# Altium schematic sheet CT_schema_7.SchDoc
size 372 x 245 mm
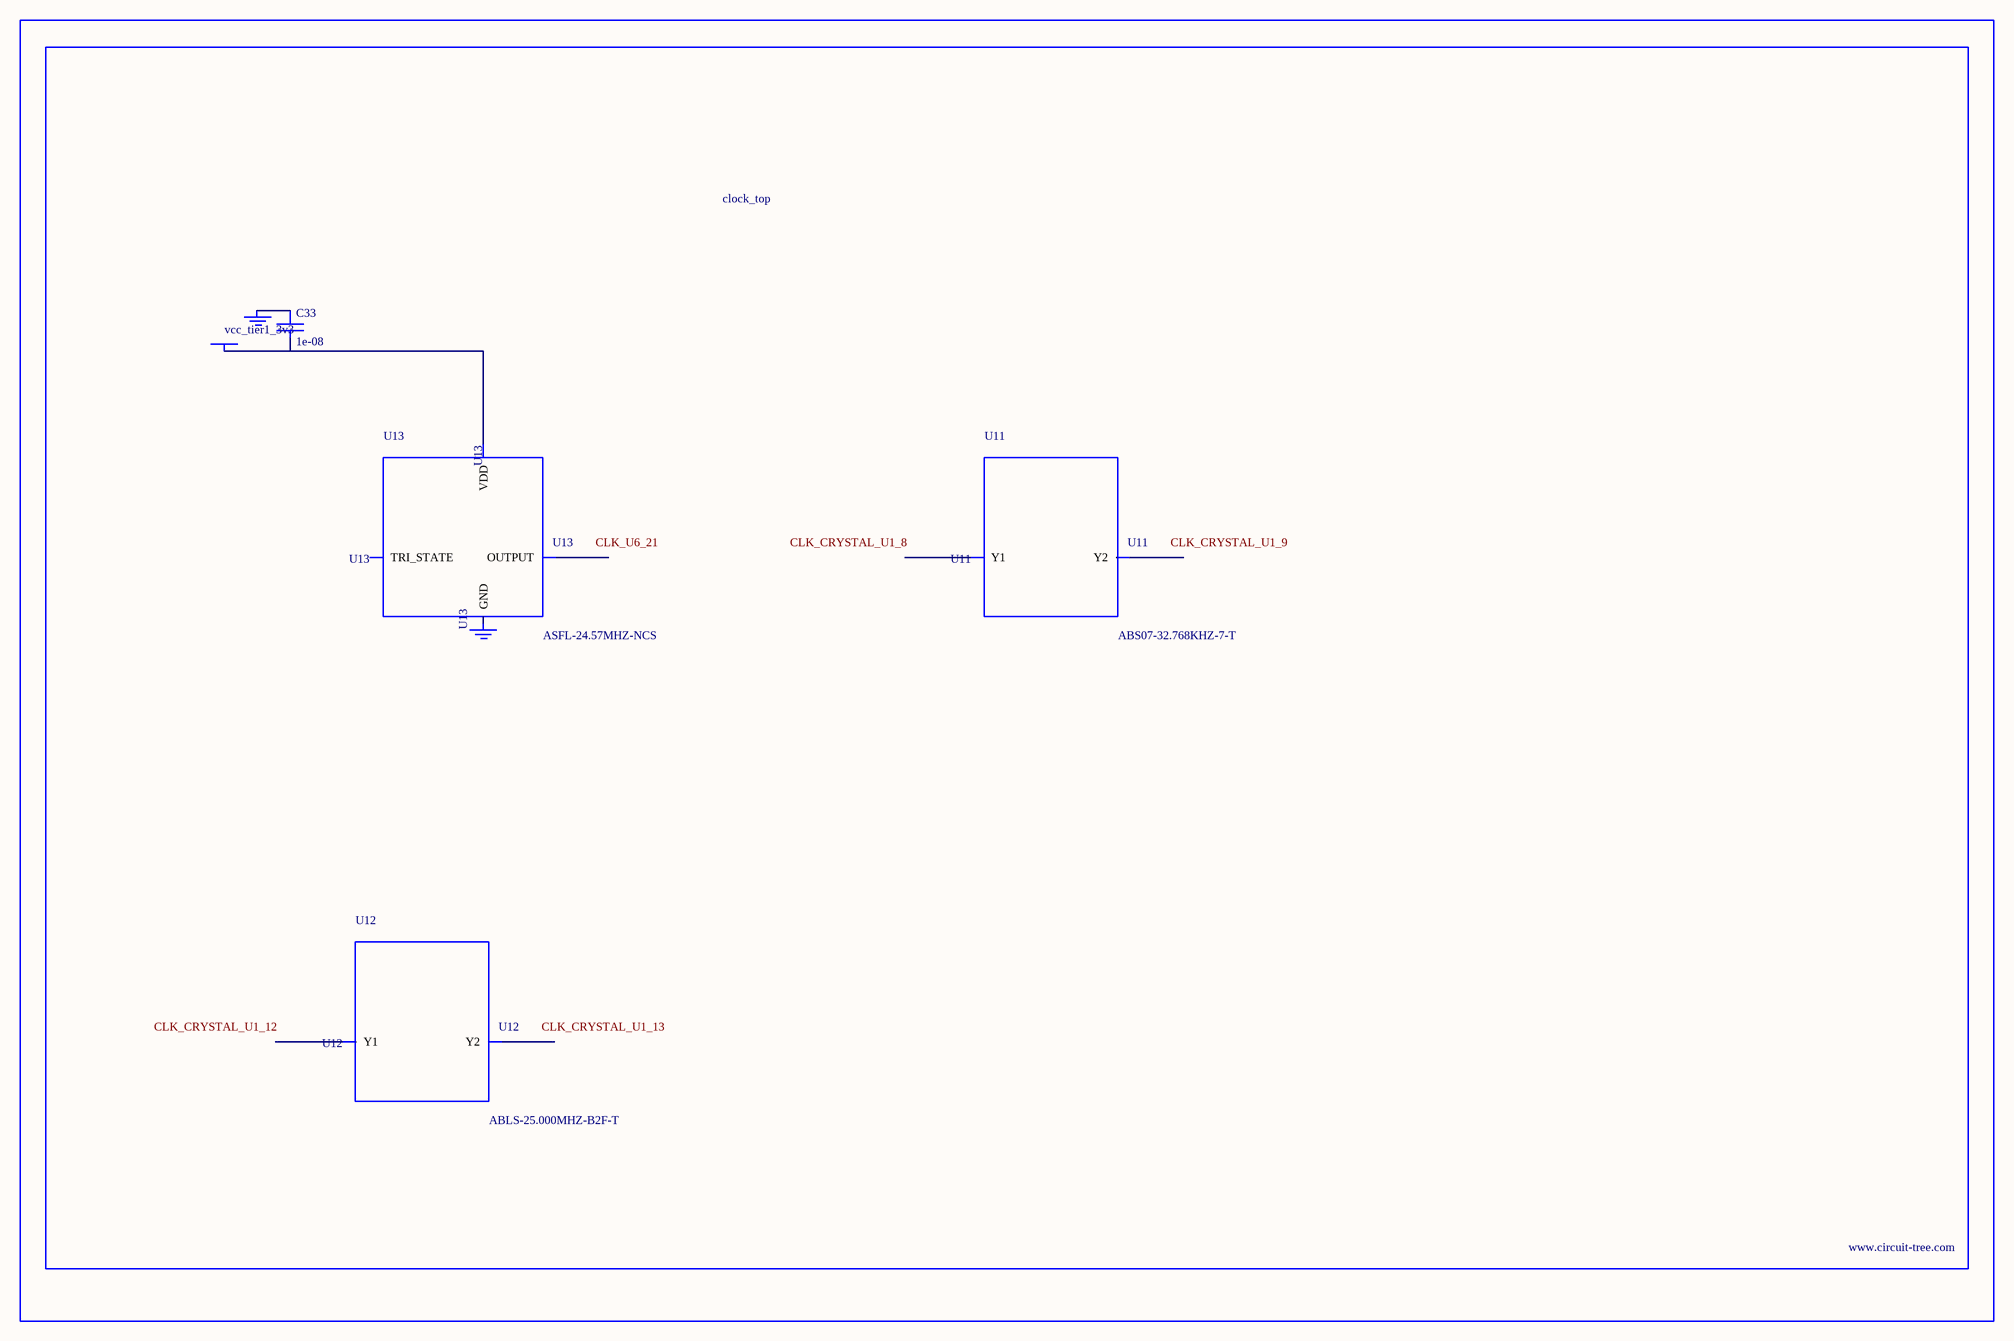
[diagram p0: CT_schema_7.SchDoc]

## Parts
BORDER6  (no value)
C33  1e-08  [C0402]
GND_INSTANCE_6_0  (no value)
GND_INSTANCE_6_1  (no value)
POWER_INSTANCE_6_0  vcc_tier1_3v3
U11  ABS07-32.768KHZ-7-T  [ABS07-32.768KHZ-7-T]
U12  ABLS-25.000MHZ-B2F-T  [ABLS-25.000MHZ-B2F-T]
U13  ASFL-24.57MHZ-NCS  [ASFL1]

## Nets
NetC33_1: C33.1 GND_INSTANCE_6_0.0(GND)
NetC33_2: C33.2 POWER_INSTANCE_6_0.0(PWR) U13.4(VDD)

Not connected (* = marked no-connect by the designer): GND_INSTANCE_6_1 0(GND); U11 1(Y1) 2(Y2); U12 1(Y1) 2(Y2); U13 1(TRI_STATE) 2(GND) 3(OUTPUT)

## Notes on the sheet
- Labels drawn without touching a wire or pin: CLK_CRYSTAL_U1_8, CLK_CRYSTAL_U1_9, CLK_CRYSTAL_U1_12, CLK_CRYSTAL_U1_13, CLK_U6_21

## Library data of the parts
BORDER6 = BORDER_PAGE6
C33 = C0402C103K3RAC
GND_INSTANCE_6_0 GND_INSTANCE_6_1 = GND
POWER_INSTANCE_6_0 = PWR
